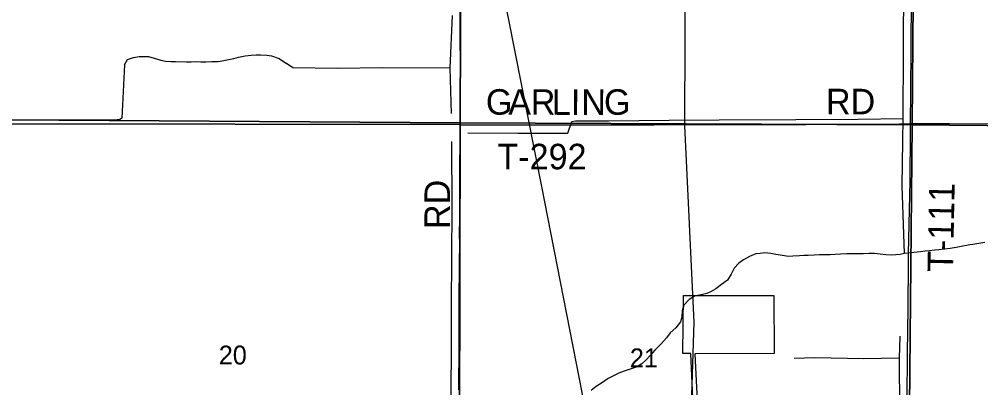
# Model space of a CAD drawing. Extents: x 0 to 34, y 0 to 22.
# Drawn here: x 2.522 to 4.664, y 18.485 to 19.306 of the extents above; entities that cross this region are included whole.
import ezdxf

# ---------------------------------------------------------------- set-up
doc = ezdxf.new("R2010")
doc.units = 0
for name, color, linetype in [('GM_X_Corporation', 7, 'Continuous'), ('GM_X_County_Road', 7, 'Continuous'), ('GM_X_County_Road_Text', 7, 'Continuous'), ('GM_X_Major_River', 7, 'Continuous'), ('GM_X_Minor_River', 7, 'Continuous'), ('GM_X_Rail_Line', 7, 'Continuous'), ('GM_X_Section', 7, 'Continuous'), ('GM_X_Section_Text', 7, 'Continuous'), ('GM_X_Township_Road', 7, 'Continuous'), ('GM_X_Township_Road_Text', 7, 'Continuous'), ('GM_X_US_Route', 7, 'Continuous')]:
    doc.layers.add(name, color=color, linetype=linetype)

msp = doc.modelspace()

# ---------------------------------------------------------------- linework, layer by layer
at = {"layer": 'GM_X_Corporation'}
msp.add_lwpolyline([(4.0371, 18.1351), (4.0177, 18.5611), (4.0005, 18.5608), (4.0014, 18.6903), (4.019, 18.6903), (4.2031, 18.6907), (4.2037, 18.561), (4.0268, 18.5601), (4.0518, 18.0509)], dxfattribs=at)
at = {"layer": 'GM_X_County_Road'}
for points in [[(3.5048, 19.0707), (3.5048, 19.0947), (3.5048, 19.104), (3.5048, 19.173), (3.5048, 19.2159), (3.5047, 19.2551), (3.5045, 19.2887), (3.5044, 19.3154), (3.5042, 19.3353), (3.504, 19.3713), (3.504, 19.408), (3.5037, 19.4559), (3.5038, 19.4764), (3.5035, 19.5168), (3.5037, 19.5347), (3.5035, 19.5565), (3.5035, 19.5744)], [(3.5013, 18.4802), (3.5016, 18.5088), (3.5021, 18.5505), (3.5022, 18.5884), (3.5025, 18.6394), (3.5025, 18.6506), (3.5024, 18.6792), (3.5025, 18.6916), (3.5032, 18.7437), (3.5032, 18.7685), (3.5035, 18.7996), (3.5034, 18.8294), (3.5038, 18.8592), (3.5038, 18.8785), (3.5037, 18.9152), (3.504, 18.9395), (3.504, 18.9587), (3.5043, 19.0495), (3.5048, 19.0698), (3.5048, 19.0707)]]:
    msp.add_lwpolyline(points, dxfattribs=at)
at = {"layer": 'GM_X_Major_River'}
for points in [[(4.6728, 18.8081), (4.6591, 18.8062), (4.6462, 18.8042), (4.6396, 18.803), (4.62, 18.7995), (4.6089, 18.7971), (4.5952, 18.7948), (4.5827, 18.7932), (4.5702, 18.7924), (4.5603, 18.7915), (4.5493, 18.7898), (4.5398, 18.7889), (4.5292, 18.7877), (4.5144, 18.7858), (4.5033, 18.7845), (4.4939, 18.784), (4.4843, 18.7816), (4.4745, 18.781), (4.4642, 18.7805), (4.4525, 18.7812), (4.4397, 18.7826), (4.4261, 18.7837), (4.4147, 18.784), (4.4022, 18.7835), (4.3912, 18.783), (4.3783, 18.783), (4.3655, 18.7833), (4.3518, 18.7825), (4.3393, 18.7816), (4.3283, 18.7808), (4.3154, 18.7811), (4.3044, 18.781), (4.2927, 18.7801), (4.2794, 18.7793), (4.2695, 18.7792), (4.2597, 18.7786), (4.2453, 18.7778), (4.2354, 18.7773), (4.2222, 18.7792), (4.2075, 18.7814), (4.1958, 18.7836), (4.1826, 18.7851), (4.1723, 18.7838)], [(4.1723, 18.7838), (4.1625, 18.7829), (4.1483, 18.7775), (4.1353, 18.7699), (4.1245, 18.7622), (4.1143, 18.751), (4.1076, 18.7375), (4.0993, 18.7248), (4.0862, 18.7145), (4.0738, 18.705), (4.0631, 18.6995), (4.0535, 18.6948), (4.0375, 18.691), (4.0276, 18.6894), (4.0145, 18.6817), (4.0025, 18.6691), (3.9987, 18.6559), (3.998, 18.6419), (3.9947, 18.6319), (3.9849, 18.6183), (3.9721, 18.6068), (3.9639, 18.5957), (3.9519, 18.5827), (3.9375, 18.5686), (3.9277, 18.5567), (3.9188, 18.5467), (3.9087, 18.5382), (3.8983, 18.5316), (3.8853, 18.5273), (3.872, 18.5227), (3.8594, 18.5181), (3.8471, 18.5123), (3.8341, 18.5054), (3.821, 18.4966), (3.8071, 18.4875), (3.7963, 18.479)]]:
    msp.add_lwpolyline(points, dxfattribs=at)
at = {"layer": 'GM_X_Minor_River'}
for points in [[(4.4939, 18.784), (4.4885, 18.9348), (4.49, 19.034), (4.4911, 19.0846), (4.4917, 19.233), (4.4923, 19.392)], [(3.4864, 19.3143), (3.4816, 19.1971), (3.4844, 19.0957)], [(2.7567, 19.2043), (2.7639, 19.2159), (2.7766, 19.2209), (2.7896, 19.2232), (2.8104, 19.2226), (2.8232, 19.2192), (2.8379, 19.2149), (2.8485, 19.2127), (2.8602, 19.2116), (2.8701, 19.2117), (2.8951, 19.211), (2.9054, 19.2111), (2.9164, 19.2115), (2.927, 19.2112), (2.938, 19.2113), (2.9513, 19.2117), (2.9658, 19.212), (2.9779, 19.2136), (2.9883, 19.2159), (3.0005, 19.2186), (3.0104, 19.2214), (3.0253, 19.2244), (3.0387, 19.2259), (3.0501, 19.2263), (3.0595, 19.2264), (3.074, 19.2257), (3.0845, 19.2242), (3.1015, 19.2181), (3.1179, 19.207)], [(3.4816, 19.1971), (3.3324, 19.1973), (3.2301, 19.1964), (3.1317, 19.1976), (3.1179, 19.207)], [(2.7567, 19.2043), (2.7507, 19.0855)], [(2.7507, 19.0855), (2.7454, 19.0819), (2.7403, 19.0816), (2.557, 19.0812), (2.4886, 19.0805), (2.3679, 19.0801), (2.2856, 19.0817), (2.2529, 19.0812)], [(3.5216, 19.0531), (3.6329, 19.0523), (3.7442, 19.0522), (3.7532, 19.0778), (3.7612, 19.0795), (3.8347, 19.0796), (3.9699, 19.0813), (4.0813, 19.0816), (4.2517, 19.0828), (4.3907, 19.0829), (4.4911, 19.0846)], [(3.4839, 18.4224), (3.4847, 18.5579), (3.4847, 18.6657), (3.4855, 18.7761), (3.4868, 18.8858), (3.4855, 19.0338)], [(4.4832, 18.5994), (4.482, 18.5505), (4.4829, 18.4351), (4.4793, 18.3657), (4.4801, 18.3224)], [(4.482, 18.5505), (4.4032, 18.5494), (4.2942, 18.5512), (4.2483, 18.5501)]]:
    msp.add_lwpolyline(points, dxfattribs=at)
at = {"layer": 'GM_X_Rail_Line'}
for points in [[(3.0707, 20.9), (3.1351, 20.7649), (3.2934, 20.4339), (3.3742, 20.2628), (3.4243, 20.1498), (3.4485, 20.0723), (3.4792, 19.9786), (3.5083, 19.83), (3.6846, 18.9371), (3.8463, 18.1103), (4.0848, 16.8935)], [(4.0191, 20.9), (4.0122, 20.3656), (4.0051, 19.4649), (4.0042, 19.0681), (4.0247, 18.6307), (3.9918, 17.6084), (3.9918, 17.4265), (4.095, 16.8935)]]:
    msp.add_lwpolyline(points, dxfattribs=at)
at = {"layer": 'GM_X_Section'}
for points in [[(2.509, 20.0994), (3.5083, 20.0811), (3.5044, 19.0749), (2.4993, 19.0815)], [(4.5187, 20.0828), (4.5106, 19.0706), (3.5044, 19.0749), (3.5083, 20.0811)], [(5.5144, 20.0832), (5.5091, 19.0615), (4.5106, 19.0706), (4.5187, 20.0828)], [(3.5044, 19.0749), (3.5019, 18.057), (2.4915, 18.0628), (2.4993, 19.0815)], [(4.5106, 19.0706), (4.5012, 18.0497), (3.5019, 18.057), (3.5044, 19.0749)], [(5.5091, 19.0615), (5.5052, 18.0545), (4.5012, 18.0497), (4.5106, 19.0706)]]:
    msp.add_lwpolyline(points, close=True, dxfattribs=at)
at = {"layer": 'GM_X_Township_Road'}
for points in [[(4.507, 19.0731), (4.5072, 19.0961), (4.5077, 19.1228), (4.5079, 19.1782), (4.5084, 19.2093), (4.5086, 19.2515), (4.5088, 19.2832), (4.5091, 19.3112), (4.5092, 19.3311), (4.5098, 19.364), (4.5103, 19.4175), (4.5103, 19.4598), (4.5105, 19.53), (4.5106, 19.5773), (4.5106, 19.5804)], [(3.5048, 19.0707), (3.513, 19.0706), (3.5827, 19.0705), (3.6525, 19.0707)], [(3.6525, 19.0707), (3.6685, 19.0707), (3.7167, 19.0709), (3.7807, 19.0706), (3.8535, 19.0705), (3.8864, 19.0705), (3.9362, 19.0708), (4.1824, 19.0714), (4.234, 19.0716), (4.2744, 19.0716), (4.3198, 19.0718), (4.3757, 19.0719), (4.418, 19.0722), (4.4541, 19.0723), (4.4827, 19.0726), (4.507, 19.0731)], [(4.4966, 18.0464), (4.4965, 18.1014), (4.4969, 18.1317), (4.497, 18.1584), (4.497, 18.1926), (4.4972, 18.2193), (4.4976, 18.2628), (4.4978, 18.2979), (4.498, 18.3557), (4.4991, 18.4297), (4.5004, 18.5366), (4.5008, 18.5752), (4.5012, 18.5982), (4.5019, 18.6759), (4.5026, 18.7499), (4.5029, 18.7841), (4.5042, 18.8487), (4.5057, 18.9146), (4.5062, 18.9444), (4.5065, 18.9693), (4.507, 19.0296), (4.5069, 19.065), (4.507, 19.0731)], [(4.507, 19.0731), (4.5094, 19.0732), (4.5262, 19.0734), (4.5579, 19.0735), (4.594, 19.0733), (4.6941, 19.073)]]:
    msp.add_lwpolyline(points, dxfattribs=at)
at = {"layer": 'GM_X_US_Route'}
for points in [[(3.5011, 18.4808), (3.5014, 18.5094), (3.5019, 18.551), (3.5019, 18.589), (3.5023, 18.64), (3.5023, 18.6512), (3.5022, 18.6798), (3.5023, 18.6922), (3.5029, 18.7442), (3.503, 18.769), (3.5033, 18.8001), (3.5031, 18.83), (3.5036, 18.8598), (3.5036, 18.8791), (3.5035, 18.9158), (3.5038, 18.94), (3.5038, 18.9593), (3.5041, 19.05), (3.5046, 19.0703), (3.5046, 19.0712), (2.5014, 19.0729)], [(2.5014, 19.0729), (3.5046, 19.0712), (3.5046, 19.0703), (3.5041, 19.05), (3.5038, 18.9593), (3.5038, 18.94), (3.5035, 18.9158), (3.5036, 18.8791), (3.5036, 18.8598), (3.5031, 18.83), (3.5033, 18.8001), (3.503, 18.769), (3.5029, 18.7442), (3.5023, 18.6922), (3.5022, 18.6798), (3.5023, 18.6512), (3.5023, 18.64), (3.5019, 18.589), (3.5019, 18.551), (3.5014, 18.5094), (3.5011, 18.4808)]]:
    msp.add_lwpolyline(points, dxfattribs=at)

# ---------------------------------------------------------------- texts
at = {"layer": 'GM_X_County_Road_Text'}
msp.add_text('RD', height=0.05682, rotation=90, dxfattribs=at).set_placement((3.4816, 18.8385))
at = {"layer": 'GM_X_Section_Text'}
for s, p in [('20', (2.9669, 18.5368)), ('21', (3.8823, 18.5305))]:
    msp.add_text(s, height=0.04186, rotation=0, dxfattribs=at).set_placement(p)
at = {"layer": 'GM_X_Township_Road_Text'}
for s, height, rotation, p in [('G', 0.0568, 359.8361, (3.5615, 19.0933)), ('A', 0.0568, 359.8347, (3.6115, 19.0932)), ('R', 0.0568, 359.8378, (3.6615, 19.093)), ('L', 0.0568, 359.8329, (3.7082, 19.0929)), ('I', 0.0568, 359.8379, (3.7507, 19.0928)), ('N', 0.0568, 359.8667, (3.774, 19.0927)), ('G', 0.0568, 0.7453, (3.825, 19.0926)), ('RD', 0.05682, 0, (4.3189, 19.0941)), ('T-292', 0.05682, 0, (3.5873, 18.9715)), ('T-111', 0.05682, 88.8715, (4.6017, 18.7423))]:
    msp.add_text(s, height=height, rotation=rotation, dxfattribs=at).set_placement(p)

doc.saveas('drawing.dxf')
